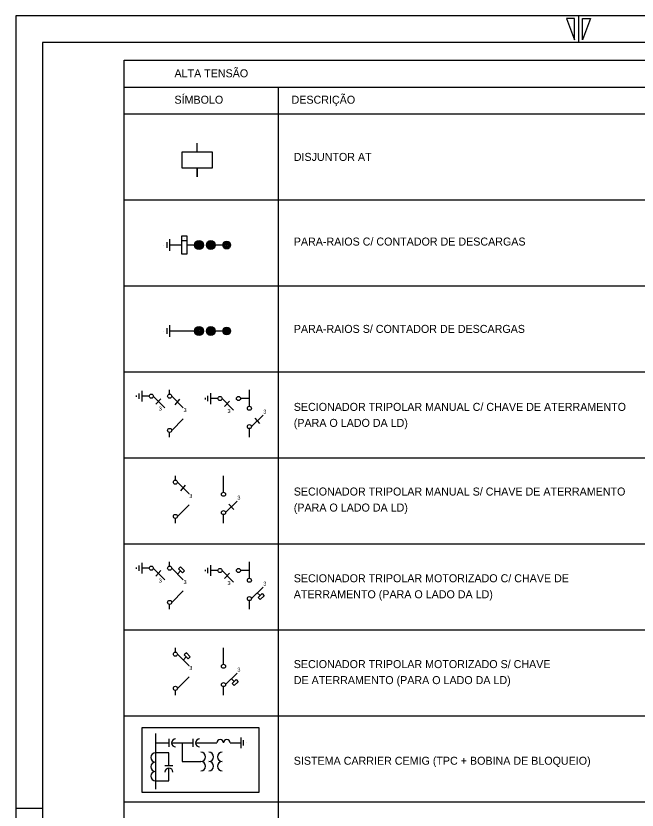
# Model space of a CAD drawing. Extents: x 563 to 3226, y 358 to 960.
# Drawn here: x 562.6 to 795.6, y 654.3 to 952 of the extents above; entities that cross this region are included whole.
import ezdxf

# ---------------------------------------------------------------- set-up
doc = ezdxf.new("R2010")
doc.units = 0
for name, color, linetype in [('Default', 7, 'Continuous'), ('Level 1', 7, 'Continuous'), ('New Level (0)', 7, 'Continuous')]:
    doc.layers.add(name, color=color, linetype=linetype)

msp = doc.modelspace()

# ---------------------------------------------------------------- linework, layer by layer
at = {"layer": 'Default'}
for p, q in [((630.56, 900.97), (630.56, 904.2)), ((630.56, 900.97), (630.56, 904.2)), ((624.94, 894.85), (624.94, 900.97)), ((624.94, 900.97), (636.18, 900.97)), ((636.18, 900.97), (636.18, 894.85)), ((636.18, 894.85), (624.94, 894.85)), ((630.56, 894.85), (630.56, 891.63)), ((630.56, 891.63), (630.56, 894.85)), ((624.68, 869.37), (624.68, 862.77)), ((626.88, 869.37), (624.68, 869.37)), ((626.88, 862.77), (626.88, 869.37)), ((619.18, 867.17), (619.18, 864.97)), ((620.28, 863.87), (620.28, 868.27)), ((624.68, 867.72), (626.88, 867.72)), ((625.78, 868.55), (625.78, 868.55)), ((618.08, 866.07), (618.08, 866.07)), ((624.68, 866.07), (620.28, 866.07)), ((631.28, 866.07), (626.88, 866.07)), ((641.64, 866.07), (635.68, 866.07)), ((624.68, 862.77), (626.88, 862.77)), ((618.08, 833.85), (618.08, 833.85)), ((619.18, 834.95), (619.18, 832.75)), ((620.28, 831.65), (620.28, 836.05)), ((626.88, 833.85), (620.28, 833.85)), ((631.28, 833.85), (626.88, 833.85)), ((641.64, 833.85), (635.68, 833.85)), ((608.77, 808.4), (608.77, 810.44)), ((609.8, 811.47), (609.8, 807.37)), ((635.57, 810.59), (635.57, 806.49)), ((607.76, 809.66), (607.76, 809.12)), ((612.59, 809.42), (609.8, 809.42)), ((618.46, 805.08), (614.12, 809.42)), ((615.12, 806.47), (616.91, 808.49)), ((625.37, 805.08), (621.03, 809.42)), ((622.3, 806.24), (624.1, 808.26)), ((633.53, 808.78), (633.53, 808.24)), ((634.54, 807.51), (634.54, 809.56)), ((638.36, 808.54), (635.57, 808.54)), ((644.24, 804.2), (639.9, 808.54)), ((640.89, 805.59), (642.68, 807.61)), ((650.17, 808.54), (646.84, 808.54)), ((625.37, 800.94), (621.03, 796.6)), ((655.28, 802.36), (650.94, 798.02)), ((652.21, 801.2), (654, 799.18)), ((627.53, 772.85), (623.19, 777.19)), ((624.46, 774.01), (626.25, 776.03)), ((627.53, 768.71), (623.19, 764.37)), ((645.57, 770.13), (641.23, 765.79)), ((642.5, 768.97), (644.3, 766.95)), ((607.76, 745.2), (607.76, 744.67)), ((608.77, 743.94), (608.77, 745.99)), ((609.8, 747.01), (609.8, 742.92)), ((612.59, 744.96), (609.8, 744.96)), ((618.46, 740.62), (614.12, 744.96)), ((625.37, 740.62), (621.03, 744.96)), ((633.53, 744.32), (633.53, 743.78)), ((634.54, 743.06), (634.54, 745.11)), ((635.57, 746.13), (635.57, 742.03)), ((615.12, 742.02), (616.91, 744.04)), ((624.34, 743.93), (623.28, 742.87)), ((638.36, 744.08), (635.57, 744.08)), ((644.24, 739.74), (639.9, 744.08)), ((640.89, 741.14), (642.68, 743.15)), ((650.17, 744.08), (646.84, 744.08)), ((625.37, 736.48), (621.03, 732.14)), ((655.28, 737.9), (650.94, 733.56)), ((654.17, 734.67), (653.11, 735.73)), ((627.53, 708.4), (623.19, 712.74)), ((626.49, 711.7), (625.43, 710.64)), ((645.57, 705.67), (641.23, 701.33)), ((627.53, 704.25), (623.19, 699.91)), ((644.46, 702.44), (643.4, 703.5))]:
    msp.add_line(p, q, dxfattribs=at)
for points in [[(624.37, 745.44), (623.6, 744.67), (625.07, 743.19), (625.84, 743.96)], [(654.2, 733.17), (653.43, 733.93), (654.9, 735.41), (655.67, 734.64)], [(626.52, 713.21), (625.76, 712.44), (627.23, 710.96), (628, 711.73)], [(644.49, 700.94), (643.72, 701.71), (645.2, 703.18), (645.97, 702.41)]]:
    msp.add_lwpolyline(points, close=True, dxfattribs=at)
for centre, radius in [((631.28, 866.07), 1.65), ((631.28, 866.07), 1.37), ((631.28, 866.07), 1.1), ((631.28, 866.07), 0.825), ((631.28, 866.07), 0.55), ((631.28, 866.07), 0.275), ((635.68, 866.07), 1.65), ((635.68, 866.07), 1.37), ((635.68, 866.07), 1.1), ((635.68, 866.07), 0.825), ((635.68, 866.07), 0.55), ((635.68, 866.07), 0.275), ((641.64, 866.07), 1.48), ((641.64, 866.07), 1.24), ((641.64, 866.07), 0.99), ((641.64, 866.07), 0.742), ((641.64, 866.07), 0.495), ((641.64, 866.07), 0.247), ((631.28, 833.85), 1.65), ((631.28, 833.85), 1.37), ((631.28, 833.85), 1.1), ((631.28, 833.85), 0.825), ((631.28, 833.85), 0.55), ((631.28, 833.85), 0.275), ((635.68, 833.85), 1.65), ((635.68, 833.85), 1.37), ((635.68, 833.85), 1.1), ((635.68, 833.85), 0.825), ((635.68, 833.85), 0.55), ((635.68, 833.85), 0.275), ((641.64, 833.85), 1.48), ((641.64, 833.85), 1.24), ((641.64, 833.85), 0.99), ((641.64, 833.85), 0.742), ((641.64, 833.85), 0.495), ((641.64, 833.85), 0.247), ((613.36, 809.42), 0.768), ((620.26, 809.42), 0.768), ((639.13, 808.54), 0.768), ((646.07, 808.54), 0.768), ((650.17, 804.89), 0.768), ((650.17, 798.02), 0.768), ((620.26, 796.6), 0.768), ((622.42, 777.19), 0.768), ((640.46, 772.66), 0.768), ((622.42, 764.37), 0.768), ((640.46, 765.79), 0.768), ((613.36, 744.96), 0.768), ((620.26, 744.96), 0.768), ((639.13, 744.08), 0.768), ((646.07, 744.08), 0.768), ((650.17, 740.43), 0.768), ((620.26, 732.14), 0.768), ((650.17, 733.56), 0.768), ((622.42, 712.74), 0.768), ((640.46, 708.2), 0.768), ((622.42, 699.91), 0.768), ((640.46, 701.33), 0.768)]:
    msp.add_circle(centre, radius, dxfattribs=at)
at = {"layer": 'Level 1'}
for p, q in [((614.99, 679.46), (619.99, 679.46)), ((619.99, 680.96), (619.99, 677.96)), ((620.99, 679.46), (628.99, 679.46)), ((624.99, 679.46), (624.99, 672.46)), ((628.99, 680.96), (628.99, 677.96)), ((629.99, 679.46), (637.99, 679.46)), ((642.99, 679.46), (646.99, 679.46)), ((646.99, 681.46), (646.99, 677.46)), ((647.99, 678.46), (647.99, 680.46)), ((648.99, 679.46), (648.99, 679.46)), ((619.99, 675.8), (614.99, 675.8)), ((619.99, 671.05), (619.99, 675.8)), ((618.49, 671.05), (621.49, 671.05)), ((619.99, 665.3), (619.99, 670.05)), ((624.99, 672.46), (631.99, 672.46)), ((614.99, 665.3), (619.99, 665.3))]:
    msp.add_line(p, q, dxfattribs=at)
for centre, radius, start, end in [((622.49, 679.46), 1.5, 90, 270), ((631.49, 679.46), 1.5, 90, 270), ((639.24, 679.46), 1.25, 0, 180), ((641.74, 679.46), 1.25, 0, 180), ((614.99, 674.05), 1.75, 90, 270), ((631.99, 674.21), 1.75, 270, 90), ((634.99, 674.21), 1.75, 270, 90), ((639.99, 674.21), 1.75, 90, 270), ((614.99, 670.55), 1.75, 90, 270), ((619.99, 668.55), 1.5, 0, 180), ((631.99, 670.71), 1.75, 270, 90), ((634.99, 670.71), 1.75, 270, 90), ((639.99, 670.71), 1.75, 90, 270), ((614.99, 667.05), 1.75, 90, 270)]:
    msp.add_arc(centre, radius, start, end, dxfattribs=at)
at = {"layer": 'New Level (0)'}
for p, q in [((562.58, 951.96), (562.58, 357.96)), ((1403.58, 951.96), (562.58, 951.96)), ((1403.58, 951.96), (562.58, 951.96)), ((562.58, 951.96), (562.58, 357.96)), ((772.08, 950.96), (769.08, 950.96)), ((769.08, 950.96), (772.08, 942.96)), ((772.08, 942.96), (772.08, 950.96)), ((773.58, 951.96), (773.58, 941.96)), ((775.08, 942.96), (775.08, 950.96)), ((775.08, 950.96), (778.08, 950.96)), ((778.08, 950.96), (775.08, 942.96)), ((572.58, 941.96), (572.58, 367.96)), ((1393.58, 941.96), (572.58, 941.96)), ((572.58, 941.96), (572.58, 367.96)), ((603.14, 915.21), (603.14, 935.35)), ((603.14, 935.35), (1303.31, 935.35)), ((603.14, 925.28), (974.81, 925.28)), ((660.98, 925.28), (660.98, 429.83)), ((603.14, 882.98), (1303.31, 882.98)), ((603.14, 850.75), (1303.31, 850.75)), ((603.14, 818.53), (953.22, 818.53)), ((620.26, 810.19), (620.26, 811.79)), ((650.17, 805.66), (650.17, 811.79)), ((620.26, 794.03), (620.26, 795.83)), ((650.17, 794.03), (650.17, 797.25)), ((603.14, 786.3), (1303.31, 786.3)), ((622.42, 777.96), (622.42, 779.57)), ((640.46, 773.43), (640.46, 779.57)), ((640.46, 761.8), (640.46, 765.02)), ((622.42, 761.8), (622.42, 763.6)), ((603.14, 754.07), (953.22, 754.07)), ((620.26, 745.73), (620.26, 747.34)), ((650.17, 741.2), (650.17, 747.34)), ((650.17, 729.57), (650.17, 732.79)), ((620.26, 729.57), (620.26, 731.37)), ((603.14, 721.84), (1303.31, 721.84)), ((622.42, 713.5), (622.42, 715.11)), ((640.46, 708.97), (640.46, 715.11)), ((640.46, 697.34), (640.46, 700.57)), ((622.42, 697.34), (622.42, 699.15)), ((603.14, 689.61), (953.22, 689.61)), ((614.99, 683.04), (614.99, 662.19)), ((562.58, 654.96), (572.58, 654.96)), ((603.14, 657.39), (1303.31, 657.39))]:
    msp.add_line(p, q, dxfattribs=at)
for points in [[(603.14, 915.21), (807.1, 915.21), (807.1, 429.83), (603.14, 429.83)], [(609.98, 685.28), (653.76, 685.28), (653.76, 660.85), (609.98, 660.85)]]:
    msp.add_lwpolyline(points, close=True, dxfattribs=at)

# ---------------------------------------------------------------- texts
at = {"layer": 'Default'}
for s, height, p in [('ALTA TENSÃO', 3, (622.07, 928.93)), ('SÍMBOLO', 3, (622.07, 919.04)), ('DESCRIÇÃO', 3, (665.99, 919.04)), ('DISJUNTOR AT', 3, (666.82, 897.6)), ('PARA-RAIOS C/ CONTADOR DE DESCARGAS', 3, (666.82, 865.87)), ('PARA-RAIOS S/ CONTADOR DE DESCARGAS', 3, (666.82, 833.14)), ('SECIONADOR TRIPOLAR MANUAL C/ CHAVE DE ATERRAMENTO ', 3, (666.82, 803.91)), ('3', 1.5, (616.18, 804)), ('3', 1.5, (625.46, 803.46)), ('3', 1.5, (641.95, 803.11)), ('3', 1.5, (655.37, 802.89)), ('(PARA O LADO DA LD) ', 3, (666.82, 797.91)), ('SECIONADOR TRIPOLAR MANUAL S/ CHAVE DE ATERRAMENTO', 3, (666.82, 772.18)), ('3', 1.5, (627.62, 771.23)), ('3', 1.5, (645.66, 770.66)), ('(PARA O LADO DA LD)', 3, (666.82, 766.18)), ('SECIONADOR TRIPOLAR MOTORIZADO C/ CHAVE DE', 3, (666.82, 739.68)), ('3', 1.5, (616.18, 739.54)), ('3', 1.5, (625.46, 739)), ('3', 1.5, (641.95, 738.66)), ('3', 1.5, (655.37, 738.43)), ('ATERRAMENTO (PARA O LADO DA LD)', 3, (666.82, 733.68)), ('SECIONADOR TRIPOLAR MOTORIZADO S/ CHAVE', 3, (666.82, 707.51)), ('3', 1.5, (627.62, 706.78)), ('3', 1.5, (645.66, 706.2)), ('DE ATERRAMENTO (PARA O LADO DA LD)', 3, (666.82, 701.51)), ('SISTEMA CARRIER CEMIG (TPC + BOBINA DE BLOQUEIO)', 3, (666.82, 671.29))]:
    msp.add_text(s, height=height, dxfattribs=at).set_placement(p)

doc.saveas('drawing.dxf')
